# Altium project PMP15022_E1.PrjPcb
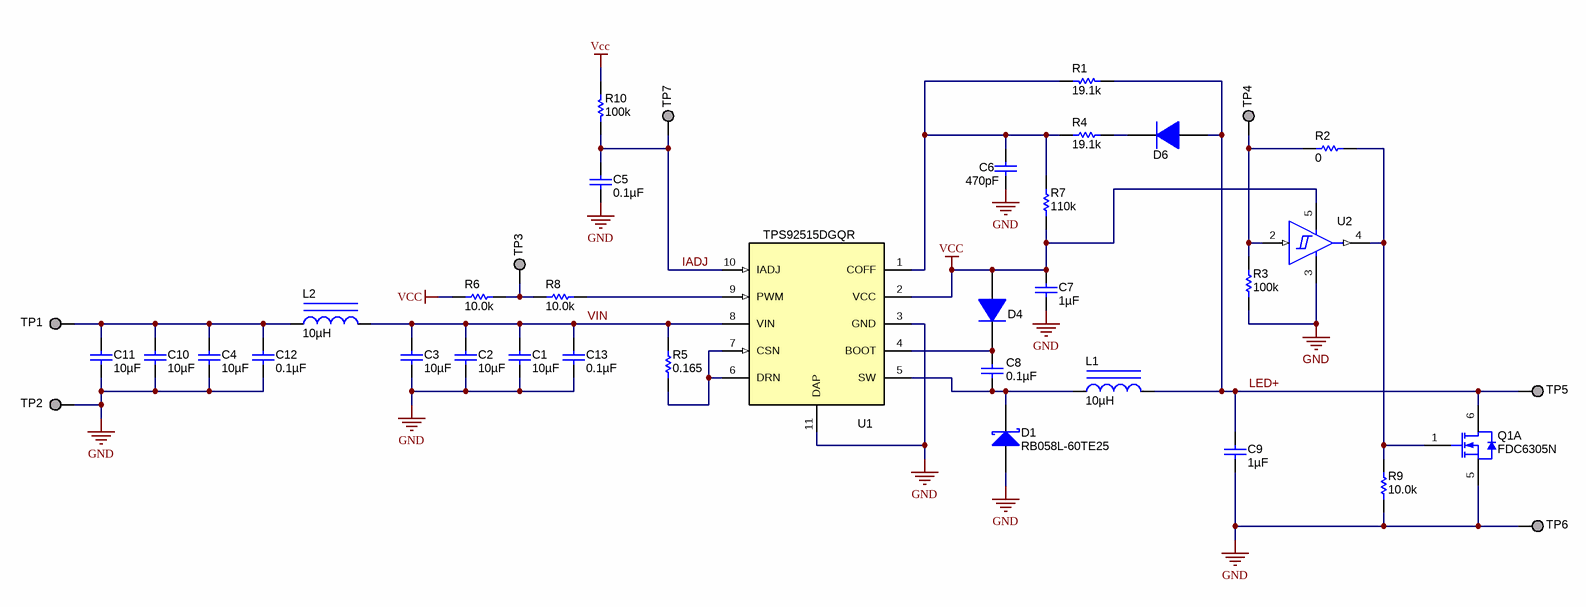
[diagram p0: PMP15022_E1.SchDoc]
CopyrightYear: 2016; PCB_Layout: Kerry Murphy; PCB_Rev: E1; PRJ_Customer: Public Release; PRJ_Engineer: Clint Jensen; PRJ_Number: PMP15022; PRJ_Title: PMP15022; SCH_Rev: E1; TechSupport: http://www.ti.com/support; TID: PMP15022
1 sheet, 38 parts. Net scope: global (net labels, ports and power ports of the same name join across sheets).
Board file: PMP15022_E1.PcbDoc

## Sheet PMP15022_E1.SchDoc
size 431 x 279 mm; Date: Not shown in title block; ApprovedBy: Not shown in title block; CheckedBy: Not shown in title block; Author: Not shown in title block; CompanyName: Not shown in title block; Engineer: Not shown in title block; Organization: Not shown in title block; Address1: Not shown in title block; Address2: Not shown in title block; Address3: Not shown in title block; Address4: Not shown in title block; DocumentNumber: 1; Revision: Use project parameter SCH_Rev; SheetNumber: 1; SheetTotal: 2; PageSetup: Record=PageOptions¦CenterHorizontal=True¦CenterVertical=True¦PrintScale=0.61¦XCorrection=1.00¦YCorrection=1.00¦PrintKind=0¦BorderSize=5000000¦LeftOffset=0¦BottomOffset=0¦Orientation=2¦PaperLength=1000¦PaperWidth=1000¦Scale=100¦PaperSource=15¦PrintQuality=600¦MediaType=1¦DitherType=10¦PrintScaleMode=1¦PaperKind=Letter

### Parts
C1  ValueDisplayed: 10µF  [1206]  (hidden comment: GRM31CR61H106KA12L)
C2  ValueDisplayed: 10µF  [1206]  (hidden comment: GRM31CR61H106KA12L)
C3  ValueDisplayed: 10µF  [1206]  (hidden comment: GRM31CR61H106KA12L)
C4  ValueDisplayed: 10µF  [1206]  (hidden comment: GRM31CR61H106KA12L)
C5  ValueDisplayed: 0.1µF  [0603_HV]  (hidden comment: GCM188R71C104KA37J)
C6  ValueDisplayed: 470pF  [0603_HV]  (hidden comment: GCM1885C1H471JA16D)
C7  ValueDisplayed: 1µF  [0603_HV]  (hidden comment: GCM188R71C105KA64D)
C8  ValueDisplayed: 0.1µF  [0603_HV]  (hidden comment: GCM188R71C104KA37J)
C9  ValueDisplayed: 1µF  [1206]  (hidden comment: GRM31CR72A105KA01L)
C10  ValueDisplayed: 10µF  [1206]  (hidden comment: GRM31CR61H106KA12L)
C11  ValueDisplayed: 10µF  [1206]  (hidden comment: GRM31CR61H106KA12L)
C12  ValueDisplayed: 0.1µF  [0603_HV]  (hidden comment: GRM188R72A104KA35D)
C13  ValueDisplayed: 0.1µF  [0603_HV]  (hidden comment: GRM188R72A104KA35D)
D1  RB058L-60TE25  [SMA]
D4  MMSD4148T1G  [SOD-123]  (value not drawn)
D6  MMSD4148T1G  [SOD-123]  (value not drawn)
L1  ValueDisplayed: 10µH  [XAL4040]  (hidden comment: XAL4040-103MEB)
L2  ValueDisplayed: 10µH  [XAL4040]  (hidden comment: XAL4040-103MEB)
Q1  FDC6305N  [SSOT-6]  (part A of 2)
R1  ValueDisplayed: 19.1k  [0603_HV]  (hidden comment: RC0603FR-0719K1L)
R2  ValueDisplayed: 0  [0603_HV]  (hidden comment: CRCW06030000Z0EA)
R3  ValueDisplayed: 100k  [0603_HV]  (hidden comment: CRCW0603100KFKEA)
R4  ValueDisplayed: 19.1k  [0603_HV]  (hidden comment: RC0603FR-0719K1L)
R5  ValueDisplayed: 0.165  [1206]  (hidden comment: PT1206FR-070R165L)
R6  ValueDisplayed: 10.0k  [0603_HV]  (hidden comment: CRCW060310K0FKEA)
R7  ValueDisplayed: 110k  [0603_HV]  (hidden comment: CRCW0603110KFKEA)
R8  ValueDisplayed: 10.0k  [0603_HV]  (hidden comment: CRCW060310K0FKEA)
R9  ValueDisplayed: 10.0k  [0603_HV]  (hidden comment: CRCW060310K0FKEA)
R10  ValueDisplayed: 100k  [0603_HV]  (hidden comment: CRCW0603100KFKEA)
TP1  TESTPOINT  [Harwin_S2751-46R]  (value not drawn)  (no BOM)
TP2  TESTPOINT  [Harwin_S2751-46R]  (value not drawn)  (no BOM)
TP3  TESTPOINT  [Harwin_S2751-46R]  (value not drawn)  (no BOM)
TP4  TESTPOINT  [Harwin_S2751-46R]  (value not drawn)  (no BOM)
TP5  TESTPOINT  [Harwin_S2751-46R]  (value not drawn)  (no BOM)
TP6  TESTPOINT  [Harwin_S2751-46R]  (value not drawn)  (no BOM)
TP7  TESTPOINT  [Harwin_S2751-46R]  (value not drawn)  (no BOM)
U1  TPS92515DGQR  [DGQ0010E_N]
U2  SN74LVC1G17DCKR  [DCK0005A_N]  (value not drawn)

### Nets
GND: C1.2 C2.2 C3.2 C4.2 C5.1 C6.2 C7.2 C9.2 C10.2 C11.2 C12.2 C13.2 D1.2(A) Q1.5(S) R3.1 R9.1 TP2.1 TP6.1 U1.3(GND) U1.11(DAP) U2.3(GND)
Vcc: C7.1 D4.2(A) R6.1 R7.1 R10.2 U1.2(VCC) U2.5(VCC)
IADJ: C5.2 R10.1 TP7.1 U1.10(IADJ)
LED+: C9.1 D6.2(A) L1.2 Q1.6(D) R1.1 TP5.1
VIN: C1.1 C2.1 C3.1 C13.1 L2.2 R5.2 U1.8(VIN)
NetC4_1: C4.1 C10.1 C11.1 C12.1 L2.1 TP1.1
NetC6_1: C6.1 R1.2 R4.1 R7.2 U1.1(COFF)
NetC8_1: C8.1 D1.1(K) L1.1 U1.5(SW)
NetC8_2: C8.2 D4.1(K) U1.4(BOOT)
NetD6_1: D6.1(K) R4.2
NetQ1_1: Q1.1(G) R2.2 R9.2 U2.4(Y)
NetR2_1: R2.1 R3.2 TP4.1 U2.2(A)
NetR5_1: R5.1 U1.6(DRN) U1.7(CSN)
NetR6_2: R6.2 R8.1 TP3.1
NetR8_2: R8.2 U1.9(PWM)

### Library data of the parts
C1-C4 C10 C11 = GRM31CR61H106KA12L: CAP, CERM, 10 µF, 50 V, +/- 10%, X5R, 1206; Manufacturer: MuRata; Polarized: N; CompType: Capacitor; Value: 10uF; U/M: EA; Cap_F: 0.00001; Tolerance_%: 10; Value1: Unknown; VDC_V: 50; Value2: 50V; TaMin_C: -55; TaMax_C: 85; AEC Category: Q200; SizeArea_mm2: 5.12; SizeAreaWB_mm2: 10.92; SizeX_mm: 3.2; SizeY_mm: 1.6; SizeZ_mm: 1.8
C5 C8 = GCM188R71C104KA37J: CAP, CERM, 0.1 µF, 16 V, +/- 10%, X7R, 0603_095; Manufacturer: MuRata; Polarized: N; CompType: Capacitor; Value: 0.1uF; U/M: EA; Cap_F: 0.0000001; Tolerance_%: 10; Value1: Unknown; VDC_V: 16; Value2: 16V; TaMin_C: -55; TaMax_C: 125; Cap_Case: 0603
C6 = GCM1885C1H471JA16D: CAP, CERM, 470 pF, 50 V, +/- 5%, C0G/NP0, 0603_095; Manufacturer: MuRata; Polarized: N; CompType: Capacitor; Value: 470pF; U/M: EA; Cap_F: 0.00000000047; Tolerance_%: 5; Value1: Unknown; VDC_V: 50; Value2: 50V; TaMin_C: -55; TaMax_C: 125; Cap_Case: 0603
C7 = GCM188R71C105KA64D: CAP, CERM, 1 µF, 16 V, +/- 10%, X7R, 0603_095; Manufacturer: MuRata; Polarized: N; CompType: Capacitor; Value: 1uF; U/M: EA; Cap_F: 0.000001; Tolerance_%: 10; Value1: Unknown; VDC_V: 16; Value2: 16V; TaMin_C: -55; TaMax_C: 125; Cap_Case: 0603
C9 = GRM31CR72A105KA01L: CAP, CERM, 1 µF, 100 V, +/- 10%, X7R, 1206; Manufacturer: MuRata; Polarized: N; CompType: Capacitor; Value: 1uF; U/M: EA; Cap_F: 0.000001; Tolerance_%: 10; Value1: Unknown; VDC_V: 100; Value2: 100V; TaMin_C: -55; TaMax_C: 125; Cap_Case: 2220; SizeArea_mm2: 5.12; SizeAreaWB_mm2: 10.92; SizeX_mm: 3.2; SizeY_mm: 1.6; SizeZ_mm: 1.8; AEC Category: Q200
C12 C13 = GRM188R72A104KA35D: CAP, CERM, 0.1 µF, 100 V, +/- 10%, X7R, 0603; Manufacturer: MuRata; Polarized: N; CompType: Capacitor; Value: 0.1uF; U/M: EA; Cap_F: 0.0000001; Tolerance_%: 10; Value1: Unknown; VDC_V: 100; Value2: 100V; TaMin_C: -55; TaMax_C: 125; Cap_Case: 0603; AEC Category: Q200
D1 = RB058L-60TE25: Diode, Schottky, 60 V, 3 A, AEC-Q101, SMA; Manufacturer: Rohm; U/M: EA; Vf_V: 0.64; Value: 60V; Value1: 3A; Value2: 0.64V; Io_A: 3; Vr_V: 60; TJmax_C: 150; SizeAreaWB_mm2: 37.3428; SizeArea_mm2: 16.3228; SizeX_mm: 5.59; SizeY_mm: 2.92; SizeZ_mm: 2.87; AEC Category: Q101; AEC Qualified: Y
D4 D6 = MMSD4148T1G: Diode, Switching, 100 V, 0.2 A, SOD-123; Manufacturer: ON Semiconductor; U/M: EA; Vf_V: 1; Value: 100V; Value1: 0.2A; Value2: 1V; Io_A: 0.2; Vr_V: 100; TJmax_C: 150
L1 L2 = XAL4040-103MEB: Inductor, Shielded, Composite, 10 µH, 3 A, 0.084 ohm, SMD; Manufacturer: Coilcraft; Value: 10uH; Ind_H: 10.0E-6; Imax_A: 3; Irms: 3.1A @ 40C rise; Isat: 3A @ 30% inductance drop; DCR_ohm: 0.084; Value2: 3A; AEC Category: Q200; SizeAreaWB_mm2: 25; SizeArea_mm2: 16; SizeX_mm: 4; SizeZ_mm: 4.1
Q1 = FDC6305N: MOSFET, N-CH, 20 V, 2.7 A, SSOT-6; Manufacturer: Fairchild Semiconductor; Alternate Manufacturer: None; SymbolCreator: x0208326; U/M: EA; ChType: N; Value: 20V; VdsMax_V: 20; Value1: 0.08 ohm; Rdson45_ohm: 0.08; Value2: 3.5 nC; QgTyp_nC: 3.5; Vgs_V: 8; IdsMax_A: 2.7; SizeAreaWB_mm2: 14.82; SizeArea_mm2: 8.12; SizeX_mm: 2.8; SizeY_mm: 2.9; SizeZ_mm: 1.1; AEC Category: Q101
R1 R4 = RC0603FR-0719K1L: RES, 19.1 k, 1%, 0.1 W, 0603; Manufacturer: Yageo America; CompType: Resistor; Value: 19.1k; Res_ohm: 19100; Value_Code: 19k1; Tolerance_%: 1; Power_W: 0.1; Value2: 0.1W; VDC_V: 150; TempCo: 200 ppm/C; SizeArea_mm2: 1.28; SizeX_mm: 1.6; SizeY_mm: 0.8; EIA_Code: E96; U/M: EA; AEC Category: Q200
R2 = CRCW06030000Z0EA: RES, 0, 5%, 0.1 W, 0603; Manufacturer: Vishay-Dale; CompType: Resistor; Value: 0; Value_Code: 0000; Tolerance_%: 5; Power_W: 0.1; Value2: 0.1W; VDC_V: 75; TempCo: 200 ppm/C; SizeArea_mm2: 1.28; SizeX_mm: 1.6; SizeY_mm: 0.8; SizeZ_mm: 1; EIA_Code: E24; U/M: EA; AEC Category: Q200
R3 = CRCW0603100KFKEA: RES, 100 k, 1%, 0.1 W, 0603; Manufacturer: Vishay-Dale; CompType: Resistor; Value: 100k; Res_ohm: 100000; Tolerance_%: 1; Power_W: 0.1; Value2: 0.1W; VDC_V: 75; TempCo: 100 ppm/C; SizeArea_mm2: 1.28; SizeX_mm: 1.6; SizeY_mm: 0.8; EIA_Code: E96; U/M: EA; AEC Category: Q200
R5 = PT1206FR-070R165L: RES, 0.165, 1%, 0.25 W, 1206; Manufacturer: Yageo America; CompType: Resistor; Value: 0.165; Value_Code: R165; Tolerance_%: 1; Power_W: 0.25; Value2: 0.25W; TempCo: 75 ppm/C; SizeArea_mm2: 5.12; SizeX_mm: 3.2; SizeY_mm: 1.6; SizeZ_mm: 1.35; U/M: EA; AEC Category: Q200; AEC Qualified: N
R6 R8 = CRCW060310K0FKEA: RES, 10.0 k, 1%, 0.1 W, 0603; Manufacturer: Vishay-Dale; CompType: Resistor; Value: 10.0k; Res_ohm: 10000; Value_Code: 10k0; Tolerance_%: 1; Power_W: 0.1; Value2: 0.1W; VDC_V: 75; TempCo: 100 ppm/C; EIA_Code: E96; U/M: EA; AEC Category: Q200
R7 = CRCW0603110KFKEA: RES, 110 k, 1%, 0.1 W, 0603; Manufacturer: Vishay-Dale; CompType: Resistor; Value: 110k; Res_ohm: 110000; Tolerance_%: 1; Power_W: 0.1; Value2: 0.1W; VDC_V: 75; TempCo: 100 ppm/C; SizeArea_mm2: 1.28; SizeX_mm: 1.6; SizeY_mm: 0.8; EIA_Code: E96; U/M: EA; AEC Category: Q200
R9 = CRCW060310K0FKEA: RES, 10.0 k, 1%, 0.1 W, 0603; Manufacturer: Vishay-Dale; CompType: Resistor; Value: 10.0k; Res_ohm: 10000; Value_Code: 10k0; Tolerance_%: 1; Power_W: 0.1; Value2: 0.1W; VDC_V: 75; TempCo: 100 ppm/C; SizeArea_mm2: 1.28; SizeX_mm: 1.6; SizeY_mm: 0.8; EIA_Code: E96; U/M: EA; AEC Category: Q200
R10 = CRCW0603100KFKEA: RES, 100 k, 1%, 0.1 W, 0603; Manufacturer: Vishay-Dale; CompType: Resistor; Value: 100k; Res_ohm: 100000; Tolerance_%: 1; Power_W: 0.1; Value2: 0.1W; VDC_V: 75; TempCo: 100 ppm/C; EIA_Code: E96; U/M: EA
TP1-TP7 = S2751-46R: Test Point, SMT; Manufacturer: Harwin
U1 = TPS92515DGQR: 2-A, Buck LED Driver with Integrated N-channel FET, High-Side Current Sense, and Shunt FET PWM Dimming Capability, DGQ0010E (VSSOP-10); Alternate PartNumber: TPS92515DGQT; Manufacturer: Texas Instruments; SymbolCreator: Altium; SizeArea_mm2: 14.64; SizeAreaWB_mm2: 23.52; SizeX_mm: 4.88; SizeY_mm: 3; SizeZ_mm: 1.1; CompType: IC; U/M: EA
U2 = SN74LVC1G17DCKR: SINGLE SCHMITT-TRIGGER BUFFER, DCK0005A (SOT-5); Alternate PartNumber: SN74LVC1G17DCKT; Manufacturer: Texas Instruments; SymbolCreator: a0799628; SizeArea_mm2: 4.2; SizeAreaWB_mm2: 9.3; SizeX_mm: 2.1; SizeY_mm: 2; SizeZ_mm: 1.1; CompType: IC; U/M: EA

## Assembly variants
001: all parts fitted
